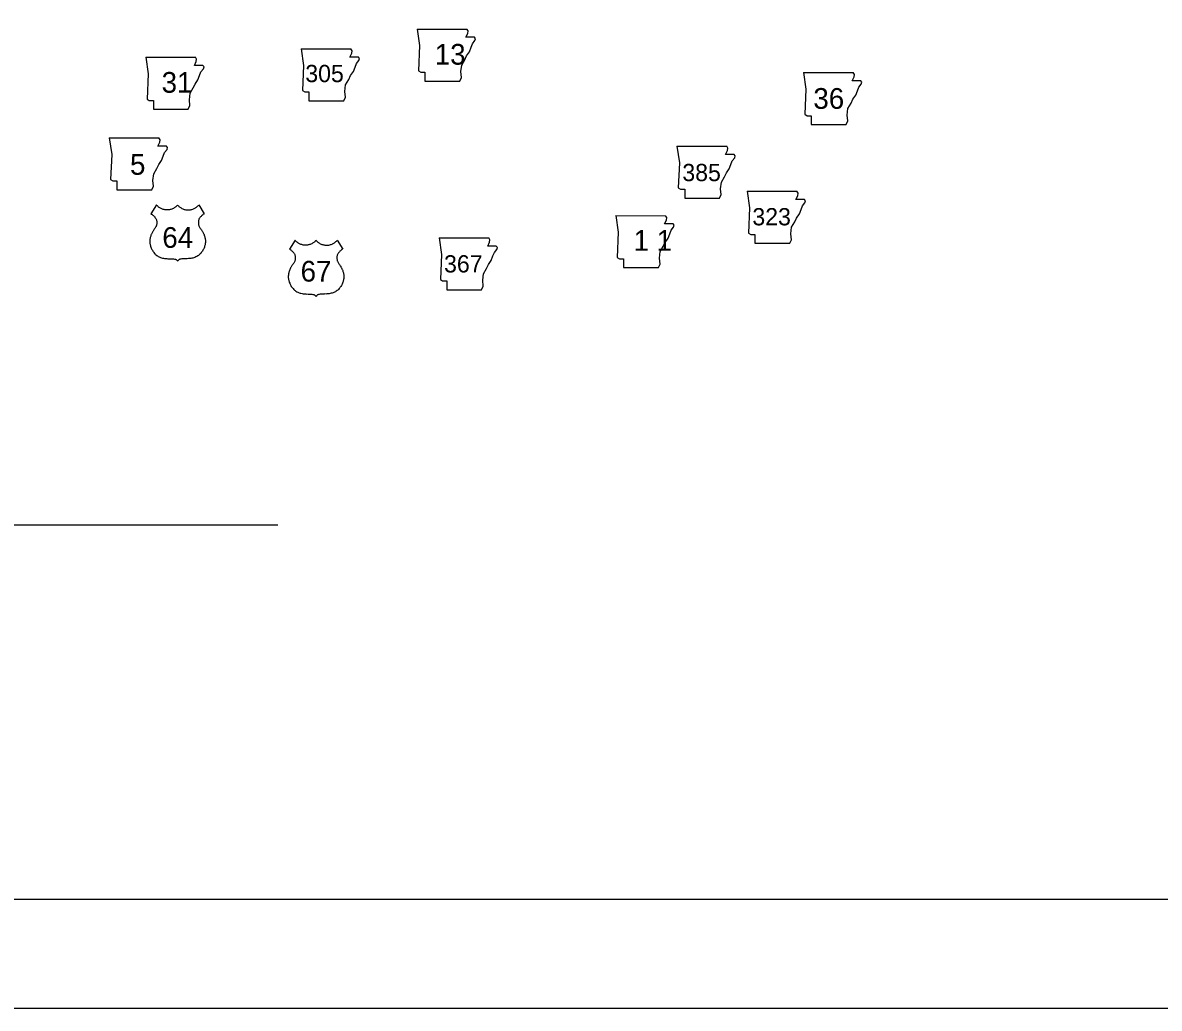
# Model space of a CAD drawing. Extents: x -819161 to 80911, y -6604 to 768454.
# Drawn here: x 45800 to 48407, y -340 to 1921 of the extents above; entities that cross this region are included whole.
import ezdxf

# ---------------------------------------------------------------- set-up
doc = ezdxf.new("R2010")
doc.units = 0
for name, color, linetype in [('21', 7, 'Continuous'), ('22', 7, 'Continuous'), ('Default', 7, 'Continuous'), ('DSN_DRFT_Junk-No-Plot', 7, 'Continuous'), ('SHET_Border-Lines', 7, 'Continuous')]:
    doc.layers.add(name, color=color, linetype=linetype)

msp = doc.modelspace()

# ---------------------------------------------------------------- linework, layer by layer
at = {"layer": '21'}
for p, q in [((46704.8, 1906.1), (46710.5, 1868)), ((46821.5, 1901.7), (46818.9, 1906.1)), ((46816.5, 1887.1), (46820.9, 1896)), ((46836.1, 1887.1), (46816.5, 1887.1)), ((46820.9, 1896), (46821.5, 1901.7)), ((46831.7, 1872.5), (46837.4, 1879.5)), ((46838.7, 1883.9), (46836.1, 1887.1)), ((46837.4, 1879.5), (46838.7, 1883.9)), ((46438.8, 1860.7), (46444.5, 1822.7)), ((46555.5, 1856.3), (46552.9, 1860.7)), ((46554.9, 1850.6), (46555.5, 1856.3)), ((46710.5, 1868), (46708, 1810.3)), ((46818.4, 1844.6), (46824.7, 1854.1)), ((46824.7, 1854.1), (46828.5, 1864.2)), ((46828.5, 1864.2), (46831.7, 1872.5)), ((46082.3, 1841.4), (46088, 1803.4)), ((46193.9, 1822.4), (46198.4, 1831.3)), ((46199, 1837), (46196.4, 1841.4)), ((46198.4, 1831.3), (46199, 1837)), ((46550.4, 1841.7), (46554.9, 1850.6)), ((46570.1, 1841.7), (46550.4, 1841.7)), ((46562.5, 1818.9), (46565.6, 1827.1)), ((46565.6, 1827.1), (46571.4, 1834.1)), ((46572.6, 1838.5), (46570.1, 1841.7)), ((46571.4, 1834.1), (46572.6, 1838.5)), ((46807, 1823.6), (46813.9, 1835.7)), ((46813.9, 1835.7), (46818.4, 1844.6)), ((46088, 1803.4), (46085.4, 1745.6)), ((46213.6, 1822.4), (46193.9, 1822.4)), ((46202.2, 1789.4), (46206, 1799.6)), ((46206, 1799.6), (46209.1, 1807.8)), ((46209.1, 1807.8), (46214.9, 1814.8)), ((46216.1, 1819.2), (46213.6, 1822.4)), ((46214.9, 1814.8), (46216.1, 1819.2)), ((46444.5, 1822.7), (46441.9, 1764.9)), ((46547.9, 1790.3), (46552.3, 1799.2)), ((46552.3, 1799.2), (46558.7, 1808.7)), ((46558.7, 1808.7), (46562.5, 1818.9)), ((46708, 1810.3), (46713.1, 1807.1)), ((46713.1, 1807.1), (46722.6, 1807.1)), ((46722.6, 1807.1), (46722.6, 1786.8)), ((46805, 1808.4), (46807, 1823.6)), ((46806.3, 1795.1), (46805, 1808.4)), ((47590.9, 1806.4), (47596.6, 1768.3)), ((47707.6, 1802), (47705, 1806.4)), ((47707, 1796.3), (47707.6, 1802)), ((46191.4, 1771), (46195.8, 1779.9)), ((46195.8, 1779.9), (46202.2, 1789.4)), ((46539, 1763), (46540.9, 1778.3)), ((46540.9, 1778.3), (46547.9, 1790.3)), ((46722.6, 1786.8), (46802.5, 1786.8)), ((46802.5, 1786.8), (46806.3, 1795.1)), ((47702.6, 1787.4), (47707, 1796.3)), ((47722.2, 1787.4), (47702.6, 1787.4)), ((47714.6, 1764.5), (47717.8, 1772.8)), ((47717.8, 1772.8), (47723.5, 1779.8)), ((47724.8, 1784.2), (47722.2, 1787.4)), ((47723.5, 1779.8), (47724.8, 1784.2)), ((46182.5, 1743.7), (46184.4, 1759)), ((46184.4, 1759), (46191.4, 1771)), ((46441.9, 1764.9), (46447, 1761.8)), ((46447, 1761.8), (46456.5, 1761.8)), ((46456.5, 1761.8), (46456.5, 1741.5)), ((46536.5, 1741.5), (46540.3, 1749.7)), ((46540.3, 1749.7), (46539, 1763)), ((47596.6, 1768.3), (47594.1, 1710.6)), ((47704.5, 1744.9), (47710.8, 1754.4)), ((47710.8, 1754.4), (47714.6, 1764.5)), ((46085.4, 1745.6), (46090.5, 1742.5)), ((46090.5, 1742.5), (46100, 1742.5)), ((46100, 1742.5), (46100, 1722.2)), ((46100, 1722.2), (46180, 1722.2)), ((46180, 1722.2), (46183.8, 1730.4)), ((46183.8, 1730.4), (46182.5, 1743.7)), ((46456.5, 1741.5), (46536.5, 1741.5)), ((47691.1, 1708.7), (47693, 1723.9)), ((47693, 1723.9), (47700, 1736)), ((47700, 1736), (47704.5, 1744.9)), ((47594.1, 1710.6), (47599.2, 1707.4)), ((47599.2, 1707.4), (47608.7, 1707.4)), ((47608.7, 1707.4), (47608.7, 1687.1)), ((47688.6, 1687.1), (47692.4, 1695.4)), ((47692.4, 1695.4), (47691.1, 1708.7)), ((47608.7, 1687.1), (47688.6, 1687.1)), ((45998.6, 1656.6), (46004.4, 1618.5)), ((46110.3, 1637.5), (46114.7, 1646.4)), ((46115.4, 1652.1), (46112.7, 1656.5)), ((46114.7, 1646.4), (46115.4, 1652.1)), ((46004.4, 1618.5), (46001.8, 1560.8)), ((46130, 1637.5), (46110.3, 1637.5)), ((46122.4, 1614.7), (46125.5, 1622.9)), ((46125.5, 1622.9), (46131.2, 1629.9)), ((46132.5, 1634.3), (46130, 1637.5)), ((46131.2, 1629.9), (46132.5, 1634.3)), ((47300.7, 1637.6), (47306.4, 1599.5)), ((47412.4, 1618.5), (47416.8, 1627.4)), ((47432.1, 1618.5), (47412.4, 1618.5)), ((47417.5, 1633.1), (47414.8, 1637.5)), ((47416.8, 1627.4), (47417.5, 1633.1)), ((47434.6, 1615.4), (47432.1, 1618.5)), ((46107.8, 1586.1), (46112.2, 1595)), ((46112.2, 1595), (46118.6, 1604.5)), ((46118.6, 1604.5), (46122.4, 1614.7)), ((47306.4, 1599.5), (47303.9, 1541.8)), ((47420.6, 1585.5), (47424.4, 1595.7)), ((47424.4, 1595.7), (47427.6, 1603.9)), ((47427.6, 1603.9), (47433.3, 1610.9)), ((47433.3, 1610.9), (47434.6, 1615.4)), ((46098.9, 1558.9), (46100.8, 1574.1)), ((46100.8, 1574.1), (46107.8, 1586.1)), ((47402.9, 1555.1), (47409.9, 1567.1)), ((47409.9, 1567.1), (47414.3, 1576)), ((47414.3, 1576), (47420.6, 1585.5)), ((46001.8, 1560.8), (46006.9, 1557.6)), ((46006.9, 1557.6), (46016.4, 1557.6)), ((46016.4, 1557.6), (46016.4, 1537.3)), ((46096.3, 1537.3), (46100.2, 1545.5)), ((46100.2, 1545.5), (46098.9, 1558.9)), ((47303.9, 1541.8), (47309, 1538.6)), ((47309, 1538.6), (47318.5, 1538.6)), ((47318.5, 1538.6), (47318.5, 1518.3)), ((47401, 1539.9), (47402.9, 1555.1)), ((47402.2, 1526.5), (47401, 1539.9)), ((46016.4, 1537.3), (46096.3, 1537.3)), ((47318.5, 1518.3), (47398.4, 1518.3)), ((47398.4, 1518.3), (47402.2, 1526.5)), ((47461.7, 1533.9), (47467.4, 1495.8)), ((47573.3, 1514.9), (47577.8, 1523.8)), ((47593, 1514.9), (47573.3, 1514.9)), ((47578.4, 1529.5), (47575.8, 1533.9)), ((47577.8, 1523.8), (47578.4, 1529.5)), ((47595.5, 1511.7), (47593, 1514.9)), ((47467.4, 1495.8), (47464.9, 1438.1)), ((47581.6, 1481.9), (47585.4, 1492)), ((47585.4, 1492), (47588.6, 1500.3)), ((47588.6, 1500.3), (47594.3, 1507.3)), ((47594.3, 1507.3), (47595.5, 1511.7)), ((47160.4, 1478.1), (47166.1, 1440)), ((47272.1, 1459.1), (47276.5, 1467.9)), ((47277.2, 1473.6), (47274.5, 1478)), ((47276.5, 1467.9), (47277.2, 1473.6)), ((47563.8, 1451.4), (47570.8, 1463.5)), ((47570.8, 1463.5), (47575.2, 1472.4)), ((47575.2, 1472.4), (47581.6, 1481.9)), ((47166.1, 1440), (47163.6, 1382.3)), ((47291.8, 1459.1), (47272.1, 1459.1)), ((47280.3, 1426.1), (47284.1, 1436.2)), ((47284.1, 1436.2), (47287.3, 1444.5)), ((47287.3, 1444.5), (47293, 1451.4)), ((47294.3, 1455.9), (47291.8, 1459.1)), ((47293, 1451.4), (47294.3, 1455.9)), ((47464.9, 1438.1), (47469.9, 1434.9)), ((47469.9, 1434.9), (47479.5, 1434.9)), ((47479.5, 1434.9), (47479.5, 1414.6)), ((47561.9, 1436.2), (47563.8, 1451.4)), ((47563.2, 1422.9), (47561.9, 1436.2)), ((46755, 1427.4), (46760.7, 1389.3)), ((46866.7, 1408.3), (46871.1, 1417.2)), ((46886.4, 1408.3), (46866.7, 1408.3)), ((46871.8, 1422.9), (46869.1, 1427.3)), ((46871.1, 1417.2), (46871.8, 1422.9)), ((46888.9, 1405.2), (46886.4, 1408.3)), ((47262.6, 1395.6), (47269.5, 1407.7)), ((47269.5, 1407.7), (47274, 1416.5)), ((47274, 1416.5), (47280.3, 1426.1)), ((47479.5, 1414.6), (47559.4, 1414.6)), ((47559.4, 1414.6), (47563.2, 1422.9)), ((46760.7, 1389.3), (46758.2, 1331.6)), ((46874.9, 1375.3), (46878.7, 1385.5)), ((46878.7, 1385.5), (46881.9, 1393.7)), ((46881.9, 1393.7), (46887.6, 1400.7)), ((46887.6, 1400.7), (46888.9, 1405.2)), ((47163.6, 1382.3), (47168.7, 1379.1)), ((47260.7, 1380.4), (47262.6, 1395.6)), ((46857.2, 1344.9), (46864.1, 1356.9)), ((46864.1, 1356.9), (46868.6, 1365.8)), ((46868.6, 1365.8), (46874.9, 1375.3)), ((47168.7, 1379.1), (47178.2, 1379.1)), ((47178.2, 1379.1), (47178.2, 1358.8)), ((47178.2, 1358.8), (47258.1, 1358.8)), ((47258.1, 1358.8), (47261.9, 1367.1)), ((47261.9, 1367.1), (47260.7, 1380.4)), ((46758.2, 1331.6), (46763.3, 1328.4)), ((46855.3, 1329.7), (46857.2, 1344.9)), ((46856.5, 1316.3), (46855.3, 1329.7)), ((46763.3, 1328.4), (46772.8, 1328.4)), ((46772.8, 1328.4), (46772.8, 1308.1)), ((46772.8, 1308.1), (46852.7, 1308.1)), ((46852.7, 1308.1), (46856.5, 1316.3))]:
    msp.add_line(p, q, dxfattribs=at)
for points in [[(46704.8, 1906.1), (46818.9, 1906.1)], [(46438.8, 1860.7), (46552.9, 1860.7)], [(46082.3, 1841.4), (46196.4, 1841.4)], [(47590.9, 1806.4), (47705, 1806.4)], [(45998.6, 1656.6), (46112.7, 1656.5)], [(47300.7, 1637.6), (47414.8, 1637.5)], [(47461.7, 1533.9), (47575.8, 1533.9)], [(47160.4, 1478.1), (47274.5, 1478)], [(46755, 1427.4), (46869.1, 1427.3)]]:
    msp.add_lwpolyline(points, dxfattribs=at)
at = {"layer": '22'}
for points in [[(46155.5, 1502.4), (46154.5, 1501.2), (46153.6, 1500.3), (46152.5, 1499.3), (46151.3, 1498.3), (46150.2, 1497.4), (46148.9, 1496.5), (46147.4, 1495.6), (46145.8, 1494.7), (46143.7, 1493.7), (46142, 1493.1), (46140.2, 1492.5), (46138.6, 1492), (46137, 1491.7), (46135.4, 1491.5), (46133.9, 1491.3), (46131.9, 1491.2), (46130.2, 1491.2), (46128.8, 1491.3), (46127.4, 1491.5), (46126, 1491.7), (46124.3, 1492), (46122.6, 1492.5), (46120.7, 1493.1), (46119, 1493.8), (46117.5, 1494.5), (46116.1, 1495.2), (46114.8, 1495.9), (46113.4, 1496.9), (46112, 1497.8), (46110.9, 1498.8), (46110, 1499.6), (46109, 1500.6), (46108, 1501.6), (46107.2, 1502.5), (46094.3, 1482.4), (46095.2, 1481.8), (46096.3, 1481.1), (46097.3, 1480.4), (46098.7, 1479.3), (46099.8, 1478.3), (46100.8, 1477.4), (46101.8, 1476.4), (46102.9, 1475.2), (46103.6, 1474.3), (46104.3, 1473.4), (46105.1, 1472.4), (46105.8, 1471.3), (46106.5, 1470), (46107, 1468.4), (46107.3, 1466.9), (46107.6, 1465.2), (46107.8, 1463.7), (46107.8, 1462.2), (46107.8, 1460.8), (46107.7, 1459.7), (46107.5, 1458.3), (46107.3, 1457.1), (46106.9, 1455.7), (46106.5, 1454.4), (46106, 1453.1), (46105.1, 1451.3), (46104.3, 1449.9), (46103.2, 1448.7), (46102, 1447), (46100.9, 1445.6), (46100, 1444.2), (46099.1, 1442.8), (46098.3, 1441.5), (46097.7, 1440.3), (46097, 1438.9), (46096.2, 1437.3), (46095.5, 1435.7), (46095, 1434.5), (46094.4, 1433), (46093.8, 1431.1), (46093.3, 1429.5), (46092.8, 1427.8), (46092.4, 1425.9), (46092.1, 1424.1), (46091.9, 1422.3), (46091.8, 1420.3), (46091.7, 1418.4), (46091.8, 1416.6), (46092, 1414.4), (46092.4, 1412.4), (46092.7, 1410.8), (46093.1, 1409.5), (46093.5, 1408), (46094.1, 1406), (46095, 1403.7), (46095.7, 1402), (46096.6, 1400.3), (46097.5, 1398.6), (46098.7, 1396.6), (46100, 1394.8), (46101.2, 1393.2), (46102.6, 1391.6), (46104.4, 1389.7), (46105.9, 1388.3), (46107.5, 1387)], [(46155.5, 1502.4), (46156.5, 1501.2), (46157.4, 1500.3), (46158.5, 1499.3), (46159.7, 1498.3), (46160.8, 1497.4), (46162.1, 1496.5), (46163.6, 1495.6), (46165.2, 1494.7), (46167.3, 1493.7), (46169, 1493.1), (46170.8, 1492.5), (46172.4, 1492), (46174, 1491.7), (46175.6, 1491.5), (46177.1, 1491.3), (46179.1, 1491.2), (46180.8, 1491.2), (46182.2, 1491.3), (46183.6, 1491.5), (46185, 1491.7), (46186.7, 1492), (46188.4, 1492.5), (46190.3, 1493.1), (46192, 1493.8), (46193.5, 1494.5), (46194.9, 1495.2), (46196.2, 1495.9), (46197.6, 1496.9), (46199, 1497.8), (46200.1, 1498.8), (46201, 1499.6), (46202, 1500.6), (46203, 1501.6), (46203.8, 1502.5), (46216.7, 1482.4), (46215.8, 1481.8), (46214.7, 1481.1), (46213.7, 1480.4), (46212.3, 1479.3), (46211.2, 1478.3), (46210.2, 1477.4), (46209.2, 1476.4), (46208.1, 1475.2), (46207.4, 1474.3), (46206.7, 1473.4), (46205.9, 1472.4), (46205.2, 1471.3), (46204.5, 1470), (46204, 1468.4), (46203.7, 1466.9), (46203.4, 1465.2), (46203.2, 1463.7), (46203.2, 1462.2), (46203.2, 1460.8), (46203.3, 1459.7), (46203.5, 1458.3), (46203.7, 1457.1), (46204.1, 1455.7), (46204.5, 1454.4), (46205, 1453.1), (46205.9, 1451.3), (46206.7, 1449.9), (46207.8, 1448.7), (46209, 1447), (46210.1, 1445.6), (46211, 1444.2), (46211.9, 1442.8), (46212.7, 1441.5), (46213.3, 1440.3), (46214, 1438.9), (46214.8, 1437.3), (46215.5, 1435.7), (46216, 1434.5), (46216.6, 1433), (46217.2, 1431.1), (46217.7, 1429.5), (46218.2, 1427.8), (46218.6, 1425.9), (46218.9, 1424.1), (46219.1, 1422.3), (46219.3, 1420.3), (46219.3, 1418.4), (46219.2, 1416.6), (46219, 1414.4), (46218.6, 1412.4), (46218.3, 1410.8), (46217.9, 1409.5), (46217.5, 1408), (46216.9, 1406), (46216, 1403.7), (46215.3, 1402), (46214.4, 1400.3), (46213.5, 1398.6), (46212.3, 1396.6), (46211, 1394.8), (46209.8, 1393.2), (46208.4, 1391.6), (46206.6, 1389.7), (46205.1, 1388.3), (46203.5, 1387)], [(46473.1, 1421.4), (46472.1, 1420.3), (46471.2, 1419.3), (46470.1, 1418.3), (46468.9, 1417.3), (46467.8, 1416.5), (46466.5, 1415.5), (46465, 1414.6), (46463.3, 1413.7), (46461.2, 1412.7), (46459.6, 1412.1), (46457.8, 1411.5), (46456.1, 1411.1), (46454.6, 1410.8), (46453, 1410.5), (46451.5, 1410.3), (46449.5, 1410.3), (46447.8, 1410.3), (46446.4, 1410.4), (46445, 1410.5), (46443.6, 1410.7), (46441.8, 1411.1), (46440.2, 1411.5), (46438.2, 1412.1), (46436.6, 1412.8), (46435.1, 1413.5), (46433.7, 1414.2), (46432.4, 1415), (46430.9, 1415.9), (46429.6, 1416.9), (46428.5, 1417.8), (46427.5, 1418.7), (46426.6, 1419.6), (46425.6, 1420.6), (46424.8, 1421.5), (46411.8, 1401.4), (46412.8, 1400.9), (46413.9, 1400.2), (46414.9, 1399.4), (46416.3, 1398.3), (46417.4, 1397.4), (46418.4, 1396.4), (46419.4, 1395.4), (46420.5, 1394.3), (46421.2, 1393.4), (46421.9, 1392.4), (46422.7, 1391.4), (46423.4, 1390.3), (46424, 1389.1), (46424.6, 1387.5), (46424.9, 1385.9), (46425.2, 1384.3), (46425.4, 1382.7), (46425.4, 1381.3), (46425.4, 1379.9), (46425.3, 1378.7), (46425.1, 1377.4), (46424.9, 1376.1), (46424.5, 1374.7), (46424.1, 1373.5), (46423.6, 1372.1), (46422.7, 1370.3), (46421.9, 1369), (46420.8, 1367.7), (46419.6, 1366.1), (46418.5, 1364.6), (46417.6, 1363.2), (46416.7, 1361.8), (46415.9, 1360.5), (46415.3, 1359.4), (46414.5, 1358), (46413.8, 1356.3), (46413.1, 1354.7), (46412.6, 1353.5), (46412, 1352), (46411.4, 1350.1), (46410.9, 1348.6), (46410.4, 1346.9), (46410, 1344.9), (46409.7, 1343.2), (46409.5, 1341.3), (46409.3, 1339.3), (46409.3, 1337.5), (46409.4, 1335.6), (46409.6, 1333.5), (46410, 1331.4), (46410.3, 1329.9), (46410.7, 1328.5), (46411.1, 1327), (46411.7, 1325.1), (46412.6, 1322.8), (46413.3, 1321.1), (46414.2, 1319.3), (46415.1, 1317.6), (46416.3, 1315.6), (46417.6, 1313.8), (46418.8, 1312.2), (46420.2, 1310.6), (46422, 1308.8), (46423.5, 1307.4), (46425.1, 1306)], [(46473.1, 1421.4), (46474.1, 1420.3), (46475, 1419.3), (46476.1, 1418.3), (46477.2, 1417.3), (46478.4, 1416.5), (46479.7, 1415.5), (46481.2, 1414.6), (46482.8, 1413.7), (46484.9, 1412.7), (46486.5, 1412.1), (46488.4, 1411.5), (46490, 1411.1), (46491.6, 1410.8), (46493.2, 1410.5), (46494.7, 1410.3), (46496.7, 1410.3), (46498.4, 1410.3), (46499.8, 1410.4), (46501.2, 1410.5), (46502.6, 1410.7), (46504.3, 1411.1), (46506, 1411.5), (46507.9, 1412.1), (46509.6, 1412.8), (46511.1, 1413.5), (46512.5, 1414.2), (46513.8, 1415), (46515.2, 1415.9), (46516.5, 1416.9), (46517.7, 1417.8), (46518.6, 1418.7), (46519.6, 1419.6), (46520.6, 1420.6), (46521.3, 1421.5), (46534.3, 1401.4), (46533.4, 1400.9), (46532.3, 1400.2), (46531.3, 1399.4), (46529.9, 1398.3), (46528.7, 1397.4), (46527.8, 1396.4), (46526.8, 1395.4), (46525.7, 1394.3), (46525, 1393.4), (46524.3, 1392.4), (46523.5, 1391.4), (46522.8, 1390.3), (46522.1, 1389.1), (46521.6, 1387.5), (46521.2, 1385.9), (46521, 1384.3), (46520.8, 1382.7), (46520.8, 1381.3), (46520.8, 1379.9), (46520.9, 1378.7), (46521.1, 1377.4), (46521.3, 1376.1), (46521.7, 1374.7), (46522.1, 1373.5), (46522.6, 1372.1), (46523.4, 1370.3), (46524.3, 1369), (46525.4, 1367.7), (46526.6, 1366.1), (46527.7, 1364.6), (46528.6, 1363.2), (46529.5, 1361.8), (46530.2, 1360.5), (46530.9, 1359.4), (46531.6, 1358), (46532.4, 1356.3), (46533.1, 1354.7), (46533.6, 1353.5), (46534.2, 1352), (46534.8, 1350.1), (46535.3, 1348.6), (46535.8, 1346.9), (46536.2, 1344.9), (46536.5, 1343.2), (46536.7, 1341.3), (46536.8, 1339.3), (46536.8, 1337.5), (46536.8, 1335.6), (46536.5, 1333.5), (46536.2, 1331.4), (46535.9, 1329.9), (46535.5, 1328.5), (46535.1, 1327), (46534.5, 1325.1), (46533.6, 1322.8), (46532.9, 1321.1), (46532, 1319.3), (46531.1, 1317.6), (46529.9, 1315.6), (46528.6, 1313.8), (46527.4, 1312.2), (46526, 1310.6), (46524.2, 1308.8), (46522.7, 1307.4), (46521.1, 1306)], [(46107.5, 1387), (46109.1, 1385.8), (46111.1, 1384.5), (46113.5, 1383.4), (46116.4, 1382.3), (46118.8, 1381.5), (46120.9, 1380.9), (46123.2, 1380.4), (46125.5, 1380), (46127.9, 1379.6), (46130.9, 1379.4), (46133.3, 1379.3), (46135.2, 1379.3), (46137.2, 1379.3), (46139.1, 1379.2), (46140.9, 1379.1), (46142.5, 1379), (46144.1, 1378.9), (46146.1, 1378.7), (46148.1, 1378.5), (46149.3, 1378.3), (46150.3, 1378.1), (46151.4, 1377.6), (46152.1, 1377.2), (46152.7, 1376.8), (46153.5, 1376.2), (46154.3, 1375.4), (46154.9, 1374.6), (46155.5, 1373.7)], [(46203.5, 1387), (46201.9, 1385.8), (46199.9, 1384.5), (46197.5, 1383.4), (46194.6, 1382.3), (46192.3, 1381.5), (46190.1, 1380.9), (46187.8, 1380.4), (46185.5, 1380), (46183.1, 1379.6), (46180.1, 1379.4), (46177.7, 1379.3), (46175.8, 1379.3), (46173.8, 1379.3), (46171.9, 1379.2), (46170.1, 1379.1), (46168.5, 1379), (46166.9, 1378.9), (46164.9, 1378.7), (46162.9, 1378.5), (46161.7, 1378.3), (46160.7, 1378.1), (46159.6, 1377.6), (46158.9, 1377.2), (46158.3, 1376.8), (46157.5, 1376.2), (46156.7, 1375.4), (46156.1, 1374.6), (46155.5, 1373.7)], [(46425.1, 1306), (46426.7, 1304.8), (46428.7, 1303.5), (46431.1, 1302.4), (46434, 1301.3), (46436.3, 1300.6), (46438.4, 1300), (46440.8, 1299.4), (46443.1, 1299), (46445.5, 1298.7), (46448.5, 1298.4), (46450.8, 1298.3), (46452.8, 1298.4), (46454.8, 1298.3), (46456.7, 1298.3), (46458.5, 1298.2), (46460.1, 1298.1), (46461.7, 1297.9), (46463.7, 1297.7), (46465.7, 1297.5), (46466.9, 1297.3), (46467.9, 1297.1), (46469, 1296.6), (46469.7, 1296.3), (46470.3, 1295.9), (46471.1, 1295.2), (46471.9, 1294.4), (46472.5, 1293.6), (46473.1, 1292.7)], [(46521.1, 1306), (46519.5, 1304.8), (46517.5, 1303.5), (46515.1, 1302.4), (46512.2, 1301.3), (46509.8, 1300.6), (46507.7, 1300), (46505.3, 1299.4), (46503.1, 1299), (46500.7, 1298.7), (46497.7, 1298.4), (46495.3, 1298.3), (46493.3, 1298.4), (46491.4, 1298.3), (46489.5, 1298.3), (46487.6, 1298.2), (46486, 1298.1), (46484.5, 1297.9), (46482.5, 1297.7), (46480.5, 1297.5), (46479.3, 1297.3), (46478.3, 1297.1), (46477.1, 1296.6), (46476.5, 1296.3), (46475.9, 1295.9), (46475.1, 1295.2), (46474.3, 1294.4), (46473.7, 1293.6), (46473.1, 1292.7)]]:
    msp.add_lwpolyline(points, dxfattribs=at)
at = {"layer": 'Default'}
msp.add_line((41170.4, 768.9), (46385.7, 768.9), dxfattribs=at)
msp.add_lwpolyline([(35278.1, 10659.9), (35278.1, -340.1), (52278.1, -340.1), (52278.1, 10659.9)], close=True, dxfattribs=at)
at = {"layer": 'DSN_DRFT_Junk-No-Plot'}
msp.add_lwpolyline([(35278.1, -340.1), (52278.1, -340.1), (52278.1, 10659.9), (35278.1, 10659.9)], close=True, dxfattribs=at)
at = {"layer": 'SHET_Border-Lines'}
msp.add_lwpolyline([(35528.1, -90.1), (52028.1, -90.1), (52028.1, 10409.9), (35528.1, 10409.9)], close=True, dxfattribs=at)
msp.add_lwpolyline([(35528.1, -90.1), (52028.1, -90.1), (52028.1, 10409.9), (35528.1, 10409.9)], close=True, dxfattribs=at)

# ---------------------------------------------------------------- texts
at = {"layer": '21'}
for s, height, p in [('13', 47.52, (46745.3, 1824.4)), ('31', 47.52, (46118.8, 1760)), ('305', 39.6, (46448.3, 1784.3)), ('36', 47.52, (47613.6, 1723.1)), ('5', 47.5, (46046.3, 1571.8)), ('385', 39.6, (47313.1, 1557.2)), ('323', 39.6, (47473.7, 1455.8)), ('1 1', 47.52, (47201.1, 1397.4)), ('367', 39.6, (46766.6, 1347.7))]:
    msp.add_text(s, height=height, dxfattribs=at).set_placement(p)
at = {"layer": '22'}
for s, p in [('64', (46120.4, 1404.2)), ('67', (46437.6, 1326.8))]:
    msp.add_text(s, height=47.52, dxfattribs=at).set_placement(p)

doc.saveas('drawing.dxf')
